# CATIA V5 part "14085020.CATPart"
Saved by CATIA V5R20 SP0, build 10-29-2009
Part number: 14085020
Definition: NONE
Nomenclature: 14085020
Source: Unknown
Description: 14085020
Bounding box of the stored display mesh (mm): x -10 to 40, y -56.5 to 46.401, z -46.6 to 46.6
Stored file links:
  C:\Users\Utente\Desktop\IO LAVORO\3D X SITO CF\X SITO\PLASTICA\RF2\14085020.CATPart
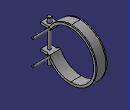
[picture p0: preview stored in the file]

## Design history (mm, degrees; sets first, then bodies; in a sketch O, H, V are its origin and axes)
Body1 "14085020" (main body)
  Solid1: solid without history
